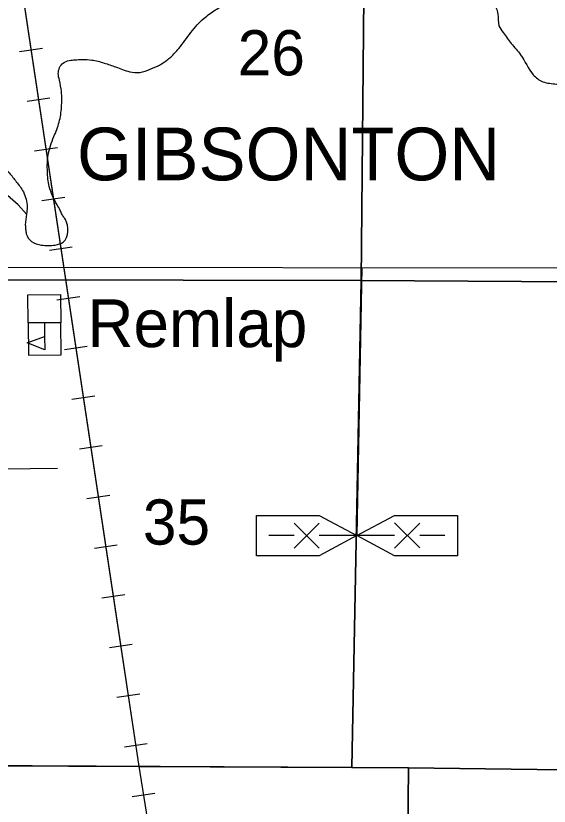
# Model space of a CAD drawing. Extents: x 380424 to 701066, y 1117407 to 1412949.
# Drawn here: x 533390 to 538699, y 1267730 to 1275597 of the extents above; entities that cross this region are included whole.
import ezdxf

# ---------------------------------------------------------------- set-up
doc = ezdxf.new("R2010")
doc.units = 0
for name, color, linetype in [('Cities Incorporated Area', 7, 'Continuous'), ('Communities and Subdivisions Names without Post Office', 7, 'Continuous'), ('Communities Names with Post Office', 7, 'Continuous'), ('Culture', 7, 'Continuous'), ('Local Roads Paved', 7, 'Continuous'), ('Local Roads Related Cells', 7, 'Continuous'), ('Narrow River Creek and Branch and Slough', 7, 'Continuous'), ('Railroads', 7, 'Continuous'), ('Section Lines', 7, 'Continuous'), ('Section Numbers', 7, 'Continuous'), ('Township  and Range lines', 7, 'Continuous')]:
    doc.layers.add(name, color=color, linetype=linetype)

msp = doc.modelspace()

# ---------------------------------------------------------------- linework, layer by layer
at = {"layer": 'Cities Incorporated Area'}
msp.add_lwpolyline([(533497.1, 1273623.6), (533412.9, 1273715.2), (533308.2, 1273809.4), (533238.4, 1273875.7), (533175.6, 1273917.6), (533081.4, 1273956), (533004.7, 1273956), (532878.4, 1273918.1), (532571.6, 1273830.2)], dxfattribs=at)
msp.add_spline([(532997.9, 1274137.1), (533123.3, 1274137.5), (533200.1, 1274130.6), (533325.7, 1274032.8), (533395.5, 1273945.5), (533465.2, 1273844.3), (533503.6, 1273694.2), (533497.1, 1273623.6)], degree=3, dxfattribs=at)
at = {"layer": 'Culture'}
for p, q in [((533838.1, 1272542), (533513.4, 1272539.7)), ((533513.4, 1272539.7), (533515.7, 1272220.1)), ((533675.7, 1272540.8), (533676.7, 1272405.5)), ((533840.4, 1272222.4), (533838.1, 1272542)), ((533515.7, 1272220.1), (533840.4, 1272222.4))]:
    msp.add_line(p, q, dxfattribs=at)
for points in [[(533838.1, 1272542), (533513.4, 1272539.7), (533511.4, 1272820.3), (533836.1, 1272822.6)], [(533677.7, 1272273.6), (533504.7, 1272343.3), (533676.7, 1272405.5)]]:
    msp.add_lwpolyline(points, close=True, dxfattribs=at)
at = {"layer": 'Local Roads Paved'}
for p, q in [((532764, 1273094.2), (549928, 1273078.2)), ((536833.3, 1273090.4), (536785.1, 1270423.6))]:
    msp.add_line(p, q, dxfattribs=at)
msp.add_lwpolyline([(533806.7, 1271091.5), (532717, 1271076.7)], dxfattribs=at)
at = {"layer": 'Local Roads Related Cells'}
for p, q in [((535785.1, 1270623.6), (536410.1, 1270623.6)), ((535785.1, 1270223.6), (535785.1, 1270623.6)), ((536410.1, 1270623.6), (536785.1, 1270423.6)), ((536785.1, 1270423.6), (537160.1, 1270623.6)), ((537160.1, 1270623.6), (537785.1, 1270623.6)), ((537785.1, 1270623.6), (537785.1, 1270223.6)), ((536160.1, 1270298.6), (536410.1, 1270548.6)), ((536410.1, 1270298.6), (536160.1, 1270548.6)), ((537410.1, 1270300.9), (537160.1, 1270550.9)), ((537160.1, 1270298.6), (537410.1, 1270548.6)), ((536160.1, 1270423.6), (535910.1, 1270423.6)), ((536785.1, 1270423.6), (536410.1, 1270223.6)), ((537160.1, 1270423.6), (536410.1, 1270423.6)), ((537160.1, 1270223.6), (536785.1, 1270423.6)), ((537660.1, 1270423.6), (537410.1, 1270423.6)), ((536410.1, 1270223.6), (535785.1, 1270223.6)), ((537785.1, 1270223.6), (537160.1, 1270223.6))]:
    msp.add_line(p, q, dxfattribs=at)
at = {"layer": 'Narrow River Creek and Branch and Slough'}
msp.add_spline([(533497.1, 1273623.6), (533485, 1273515.9), (533487.5, 1273474.7), (533494.9, 1273428.3), (533546.2, 1273350.1), (533643.9, 1273315.8), (533783.2, 1273315.8), (533861.3, 1273345.2), (533883.3, 1273570), (533861.3, 1273601.8), (533841.8, 1273638.5), (533832, 1273660.5), (533801.4, 1273715.1), (533723.5, 1273898.6), (533705.1, 1274047.8), (533712, 1274210.6), (533769.3, 1274394.2), (533822.1, 1274540), (533845, 1274686.8), (533845, 1274842.8), (533824.4, 1274955.3), (533812.9, 1275021.8), (533826.6, 1275081.4), (533861, 1275127.3), (533923, 1275152.6), (533980.3, 1275159.4), (534051.4, 1275161.7), (534147.7, 1275157.1), (534269.2, 1275127.3), (534383.9, 1275088.3), (534523.7, 1275040.1), (534626.9, 1275033.3), (534727.8, 1275065.4), (534821.8, 1275106.7), (534892.9, 1275154.8), (534931.9, 1275187), (535012.2, 1275271.8), (535133.7, 1275432.4), (535264.4, 1275572.4), (535376.8, 1275655), (535491.4, 1275716.9), (535619.8, 1275755.9), (535773.5, 1275774.3), (535961.5, 1275838.5), (536170.2, 1275921.1), (536372, 1276040.9), (536532.5, 1276112), (536702.2, 1276144.1), (536883.3, 1276160.2), (537089.7, 1276187.7), (537243.3, 1276196.9), (537500.2, 1276201.5), (537667.5, 1276203.8), (537805.1, 1276222.1), (537860.2, 1276226.7), (537910.6, 1276213), (537958.8, 1276176.3), (538016.1, 1276102.8), (538059.7, 1276020.3), (538128.5, 1275832.1), (538151.4, 1275732), (538188.1, 1275615), (538199.5, 1275498), (538240.8, 1275431.5), (538321.1, 1275321.4), (538415.1, 1275209), (538541.2, 1275009.5), (538635.2, 1274940.6), (538772.8, 1274917.7), (538919.6, 1274897), (539054.9, 1274922.3), (539194.7, 1275032.4), (539449.3, 1275227.4), (539609.8, 1275343), (539722.1, 1275414.1), (539839.1, 1275453.1), (539951.4, 1275466.9), (540017.9, 1275460), (540077.6, 1275434.8), (540105.1, 1275384.3), (540107.4, 1275343)], degree=3, dxfattribs=at)
at = {"layer": 'Railroads'}
for p, q in [((533654.5, 1275273.1), (533427.1, 1275238.8)), ((533729.1, 1274778.7), (533501.7, 1274744.4)), ((533803.6, 1274284.3), (533576.2, 1274250)), ((533878.2, 1273789.9), (533650.8, 1273755.6)), ((533952.7, 1273295.5), (533725.3, 1273261.2)), ((534027.3, 1272801.1), (533799.8, 1272766.8)), ((534101.8, 1272306.6), (533874.4, 1272272.4)), ((534176.4, 1271812.2), (533948.9, 1271777.9)), ((534250.9, 1271317.8), (534023.5, 1271283.5)), ((534325.5, 1270823.4), (534098, 1270789.1)), ((534400, 1270329), (534172.6, 1270294.7)), ((534474.6, 1269834.6), (534247.1, 1269800.3)), ((534549.1, 1269340.2), (534321.7, 1269305.9)), ((534623.6, 1268845.8), (534396.2, 1268811.5)), ((534698.2, 1268351.4), (534470.8, 1268317.1)), ((534775.2, 1267858.3), (534548, 1267822.1))]:
    msp.add_line(p, q, dxfattribs=at)
for points in [[(532494.7, 1282194.1), (534612.6, 1268147.5), (534754.6, 1267256.1)], [(533466.3, 1275750.4), (534360.8, 1269817.4)], [(534360.8, 1269817.4), (534612.6, 1268147.5), (534754.6, 1267256.1), (534842.5, 1266063.9), (534818.4, 1263850.9)]]:
    msp.add_lwpolyline(points, dxfattribs=at)
at = {"layer": 'Section Lines'}
for points in [[(536876.7, 1278265.1), (536826.1, 1272963.6), (531505.1, 1272973), (531558.7, 1278286.4), (531553.9, 1278290.5)], [(542182.1, 1278242.7), (542149.6, 1272929.1), (536826.1, 1272963.6), (536876.7, 1278265.1)], [(542149.6, 1272929.1), (542157.9, 1268050.3), (537299.9, 1268111.1), (536735.2, 1268114.2), (536826.1, 1272963.6)], [(542584.5, 1268049.1), (542547, 1262714.2), (537247, 1262765.7), (537299.9, 1268111.1), (542157.9, 1268050.3), (542577, 1268053.3)]]:
    msp.add_lwpolyline(points, close=True, dxfattribs=at)
for points in [[(531503.8, 1272478.4), (531505.1, 1272973), (536826.1, 1272963.6), (536735.2, 1268114.2), (532277.6, 1268137.6)], [(532277.6, 1268137.6), (536735.2, 1268114.2), (537299.9, 1268111.1), (537247, 1262765.7), (532013.4, 1262848.3), (532027.1, 1267992.7)]]:
    msp.add_lwpolyline(points, dxfattribs=at)
at = {"layer": 'Township  and Range lines'}
for p, q in [((532277.6, 1268137.6), (536735.2, 1268114.2)), ((536735.2, 1268114.2), (537299.9, 1268111.1)), ((537299.9, 1268111.1), (542157.9, 1268050.3))]:
    msp.add_line(p, q, dxfattribs=at)

# ---------------------------------------------------------------- texts
at = {"layer": 'Communities and Subdivisions Names without Post Office'}
msp.add_text('Remlap', height=475, rotation=0.00046, dxfattribs=at).set_placement((534103.2, 1272299.4))
at = {"layer": 'Communities Names with Post Office'}
msp.add_text('GIBSONTON', height=525, rotation=0.00047, dxfattribs=at).set_placement((533999.2, 1273959.2))
at = {"layer": 'Section Numbers'}
for s, p in [('26', (535598.5, 1275004.2)), ('35', (534654.7, 1270333.6))]:
    msp.add_text(s, height=450, dxfattribs=at).set_placement(p)

doc.saveas('drawing.dxf')
